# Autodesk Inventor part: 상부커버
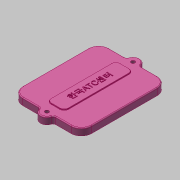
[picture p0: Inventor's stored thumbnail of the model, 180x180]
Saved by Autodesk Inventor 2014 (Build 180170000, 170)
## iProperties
Created: 2016-02
Part Number: 상부커버
Material: ABS 플라스틱
Document SubType Name: Modeling
Designer: mduedu
Density: 1.06 g/cm^3
Mass: 69.6905 g
Surface Area: 192.371 cm^2
Volume: 65.7458 cm^3
Appearance: 분홍색
Author: mduedu
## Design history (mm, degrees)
sketch "스케치1"
  geometry: L1 (40, 50)-(-40, 50); L2 (-40, 50)-(-40, -50); L3 (-40, -50)-(40, -50); L4 (40, -50)-(40, 50); L5 (40, 50)-(-40, -50); L6 (-40, 50)-(40, -50); C1 r 7.5 at (0, 50); C2 r 7.5 at (0, -50); 1 further point
  constraints: 12 end point, 4 midpoint, 2 centre point, 2 parallel, 1 horizontal, 1 perpendicular
  dimensions: "d0" = 80 distance of L2.end L3.end; "d2" = 100 distance of L1.end L2.end; "d46" = 15 diameter of C1; "d47" = 15 diameter of C2
extrude "돌출1" new body sketch "스케치1" distance "d3" = 8; taper "d4" = 0 deg
fillet "모깎기1" dims "d5" = 12, "d48" = 3
sketch "스케치9"
  geometry: L1 (28, 50)-(10.062, 50) reference; L2 (-10.062, 50)-(-28, 50) reference; L3 (-40, 38)-(-40, -38) reference; L4 (-28, -50)-(-10.062, -50) reference; L5 (10.062, -50)-(28, -50) reference; L6 (40, -38)-(40, 38) reference; A1 r 12 centre (28, 38) between (40, 38) and (28, 50) reference; A2 r 3 centre (10.062, 53) between (7.187, 52.143) and (10.062, 50) reference; A3 r 7.5 centre (0, 50) between (7.187, 52.143) and (-7.187, 52.143) reference; A4 r 3 centre (-10.062, 53) between (-10.062, 50) and (-7.187, 52.143) reference; A5 r 12 centre (-28, 38) between (-28, 50) and (-40, 38) reference; A6 r 12 centre (-28, -38) between (-40, -38) and (-28, -50) reference; A7 r 3 centre (-10.062, -53) between (-7.187, -52.143) and (-10.062, -50) reference; A8 r 7.5 centre (0, -50) between (-7.187, -52.143) and (7.187, -52.143) reference; A9 r 3 centre (10.062, -53) between (10.062, -50) and (7.187, -52.143) reference; A10 r 12 centre (28, -38) between (28, -50) and (40, -38) reference; 3 further points
  constraints: 2 coincident
hole "구멍2" sketch "스케치9" at (0, 50), (0, -50) diameter "d49" = 4.5; stored, may be unused: countersink angle "d53" = 90 deg, drill point angle "d55" = 118 deg; dims "d50" = 6, "d51" = 4, "d52" = 2, "d54" = 8
sketch "스케치3"
  geometry: L1 (10, -40)-(-10, -40); L2 (-10, -40)-(-10, 40); L3 (-10, 40)-(10, 40); L4 (10, 40)-(10, -40); L5 (10, -40)-(-10, 40); L6 (-10, -40)-(10, 40); 1 further point
  constraints: 12 end point, 2 midpoint, 2 parallel, 1 horizontal, 1 perpendicular
  dimensions: "d16" = 80 distance of L1.end L2.end; "d18" = 20 distance of L2.end L3.end
extrude "돌출2" join sketch "스케치3" distance "d19" = 1; taper "d20" = 0 deg
fillet "모깎기2" dims "d21" = 5
fillet "모깎기3" dims "d22" = 0.3
sketch "스케치4"
  geometry: 2 further points
  constraints: 1 coincident, 1 other
feature "엠보싱1" sketch "스케치4" dims "d0" = 80, "d2" = 100, "d24" = 0.5, "d25" = 0, "d46" = 15, "d47" = 15
fillet "모깎기10" dims "d45" = 1
node "솔리드1"
node "투영된 루프2"
